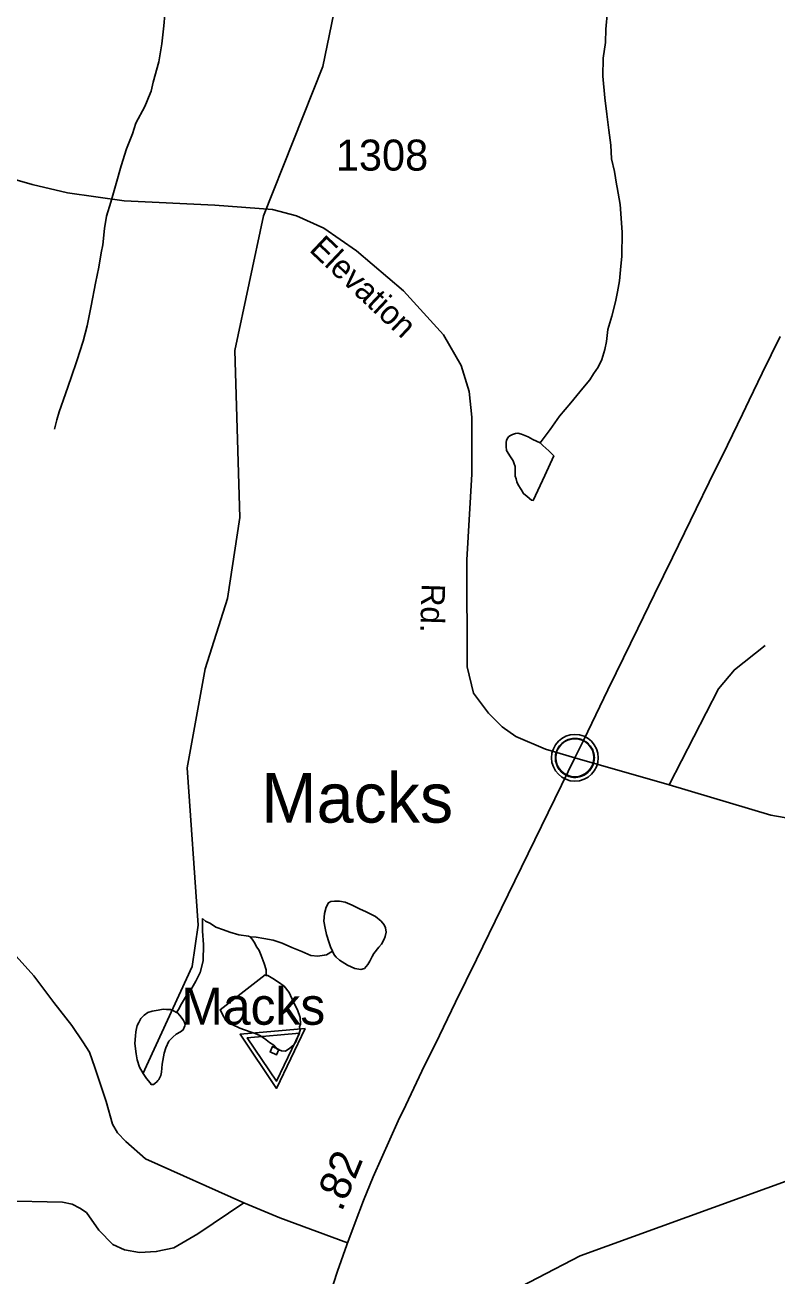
# Model space of a CAD drawing. Extents: x 2082433 to 2279600, y 546599 to 755198.
# Drawn here: x 2128894 to 2131923, y 616158 to 621201 of the extents above; entities that cross this region are included whole.
import ezdxf

# ---------------------------------------------------------------- set-up
doc = ezdxf.new("R2010")
doc.units = 0
for name, color, linetype in [('Exist Civil Demographics Community CELL', 7, 'Continuous'), ('Exist Civil Demographics Community Label', 7, 'Continuous'), ('Exist Hydrographic Creek Single Shore', 7, 'Continuous'), ('Exist Hydrographic Misc Water Feature', 7, 'Continuous'), ('Exist Road Non-System Type 51', 7, 'Continuous'), ('Exist Road Primary NC Attributed', 7, 'Continuous'), ('Exist Road Primary NC Service Mileage Hundredths English Label', 7, 'Continuous'), ('Exist Road Secondary Type 51 Attributed', 7, 'Continuous'), ('Exist Road Secondary Type 51 Label', 7, 'Continuous'), ('Exist Road Secondary Type 51 Number Label', 7, 'Continuous'), ('Exist Survey Geodetic Marker CELL', 7, 'Continuous'), ('Exist Survey Geodetic Marker Label', 7, 'Continuous')]:
    doc.layers.add(name, color=color, linetype=linetype)

msp = doc.modelspace()

# ---------------------------------------------------------------- linework, layer by layer
at = {"layer": 'Exist Civil Demographics Community CELL'}
msp.add_lwpolyline([(2131031.5, 618259.6), (2131032.5, 618265.2), (2131034.3, 618271.8), (2131037.2, 618279), (2131040.1, 618284.7), (2131043.4, 618290.5), (2131047.2, 618295.6), (2131051.2, 618300), (2131055.8, 618304.6), (2131061.3, 618309.2), (2131066.7, 618312.8), (2131071.6, 618315.7), (2131076.7, 618318.1), (2131082.1, 618320.4), (2131087.7, 618322.3), (2131092.1, 618323.4), (2131096.9, 618324.1), (2131101, 618324.9), (2131107.4, 618325.1), (2131111.8, 618325), (2131117.5, 618324.8), (2131122.4, 618324), (2131127.3, 618323), (2131132.3, 618321.6), (2131137.5, 618319.7), (2131144.1, 618316.8), (2131150.4, 618313.3), (2131155.5, 618309.7), (2131160.6, 618305.7), (2131163.9, 618302.6), (2131168.1, 618298.2), (2131171.9, 618293.5), (2131175, 618288.9), (2131178.1, 618283.9), (2131180.6, 618278.7), (2131182.6, 618273.7), (2131184.2, 618268.7), (2131185.5, 618264.1), (2131186.6, 618258.1), (2131187.2, 618253.4), (2131187.5, 618247.4), (2131187.3, 618241.6), (2131186.7, 618235.9), (2131185.8, 618230.4), (2131184.1, 618224.3), (2131182.2, 618218.4), (2131179.9, 618213.4), (2131176.8, 618207.4), (2131173.5, 618202), (2131170.1, 618197.3), (2131165.8, 618192.6), (2131160.5, 618187.6), (2131155.5, 618183.5), (2131150.5, 618180.1), (2131146.2, 618177.6), (2131139.4, 618174.3), (2131132.2, 618171.6), (2131126.3, 618170.2), (2131119.7, 618168.9), (2131115.2, 618168.4), (2131110.8, 618168.1), (2131105.2, 618168.1), (2131100.9, 618168.5), (2131095.3, 618169.3), (2131089.3, 618170.6), (2131084.7, 618171.9), (2131079.6, 618173.8), (2131075, 618175.7), (2131071.1, 618178), (2131064.3, 618182.1), (2131058.7, 618186.3), (2131053.8, 618190.8), (2131049.3, 618195.7), (2131046.1, 618199.6), (2131043.2, 618203.8), (2131039.1, 618210.9), (2131037.3, 618214.5), (2131035.6, 618218.5), (2131033, 618226.7), (2131031.5, 618233.7), (2131030.8, 618238.9), (2131030.5, 618245.2), (2131030.4, 618249.9), (2131031, 618256.4)], close=True, dxfattribs=at)
for centre, radius in [((2131109.1, 618247.2), 94.3), ((2131108.8, 618247.5), 76.7)]:
    msp.add_circle(centre, radius, dxfattribs=at)
at = {"layer": 'Exist Hydrographic Creek Single Shore'}
msp.add_lwpolyline([(2130498.7, 615818.9), (2130788.8, 616062.3), (2131129.9, 616239.1), (2132526.9, 616745.5)], dxfattribs=at)
at = {"layer": 'Exist Hydrographic Misc Water Feature'}
for points in [[(2129368.9, 616973.5), (2129566.7, 617405.8), (2129590.7, 617572.6), (2129546.9, 618206.7), (2129619.9, 618605.4), (2129709.9, 618889), (2129758.9, 619216), (2129738.8, 619888.9), (2129853.8, 620431.2), (2130092.9, 621033.2), (2130199, 621549.4), (2130195.9, 622192.5), (2130261.9, 622332.2), (2130370, 622418.6), (2130460.8, 622442.9), (2130660.9, 622452), (2130735.8, 622493.1), (2130760.8, 622545.2), (2130767, 622945.2)], [(2129012.1, 619571.6), (2129021.9, 619609.9), (2129031.6, 619641.7), (2129057.2, 619714), (2129079.2, 619780), (2129102.9, 619847.8), (2129128.2, 619926.3), (2129144.2, 619988), (2129159.5, 620068.4), (2129177.4, 620160.2), (2129191.1, 620224.3), (2129200.8, 620282.4), (2129206.5, 620314.4), (2129214.1, 620380.5), (2129222.1, 620430.4), (2129239.9, 620486.5), (2129261.4, 620562.8), (2129281.3, 620632.8), (2129303.1, 620702.5), (2129326.7, 620762.6), (2129340.6, 620804.7), (2129376.1, 620872.7), (2129398, 620925), (2129401.7, 620934.9), (2129409.9, 620971), (2129433.3, 621053), (2129445.4, 621125.1), (2129452.8, 621197.3), (2129456.5, 621243)], [(2130969.7, 619516.3), (2130993.3, 619548.5), (2131009.3, 619570.4), (2131047.2, 619624.6), (2131092.8, 619678.6), (2131140.3, 619737.1), (2131168.6, 619770.9), (2131184.4, 619795.3), (2131202.5, 619821.4), (2131217.9, 619853.1), (2131229.7, 619893.5), (2131235.9, 619925.4), (2131241.8, 619973.2), (2131257.6, 620027.6), (2131272.8, 620085.3), (2131280.8, 620125.5), (2131288.4, 620169.3), (2131292.9, 620213.7), (2131298.4, 620269.6), (2131299.9, 620365.5), (2131291.5, 620477.5), (2131279.4, 620545.4), (2131277.1, 620559.6), (2131269.1, 620611.1), (2131256.6, 620661.2), (2131254.3, 620717.1), (2131246.1, 620777.2), (2131238.2, 620841.3), (2131229.5, 620907), (2131221.1, 620995.1), (2131223, 621067), (2131232.8, 621130.8), (2131234, 621184.9), (2131239.8, 621257.1)], [(2130969.7, 619516.3), (2130939.8, 619530.2), (2130921.3, 619540.3), (2130907.4, 619546), (2130893.7, 619551.8), (2130879.3, 619556), (2130869.7, 619553.8), (2130857.6, 619550), (2130849.6, 619545.9), (2130843.4, 619541.9), (2130837.9, 619535.9), (2130833.6, 619525.6), (2130831.7, 619519.8), (2130831.7, 619511.7), (2130831.7, 619501.5), (2130833.8, 619485.8), (2130849.8, 619459.8), (2130859.8, 619443.7), (2130864.1, 619431.7), (2130868, 619421.8), (2130868, 619397.9), (2130868.2, 619382), (2130872.5, 619372.1), (2130874.4, 619360), (2130880.5, 619348.1), (2130892.8, 619328), (2130902.5, 619312), (2130916.6, 619300.1), (2130934.7, 619286), (2130940.8, 619284.3), (2130988.2, 619384.6), (2131024.1, 619464.7), (2131004, 619484.4), (2130979.6, 619506.3), (2130969.7, 619516.3)], [(2130132.7, 617467.2), (2130138.9, 617453.2), (2130146.9, 617443.1), (2130161, 617431.3), (2130193, 617411.4), (2130222.9, 617397.5), (2130247.1, 617393.9), (2130260.9, 617397.9), (2130275, 617414), (2130283, 617427.8), (2130292.7, 617445.8), (2130299, 617457.8), (2130318.7, 617484.1), (2130330.4, 617496), (2130340.6, 617516), (2130344.3, 617526.4), (2130348.2, 617544), (2130346.6, 617562.1), (2130340, 617574.1), (2130328.3, 617588), (2130306.2, 617608), (2130284, 617617.8), (2130267.8, 617625.9), (2130241.8, 617637.6), (2130212.1, 617653.5), (2130184, 617665.4), (2130160, 617669.5), (2130139.9, 617669.3), (2130125.5, 617667.4), (2130115.9, 617663.1), (2130106.3, 617645.2), (2130100.1, 617618.9), (2130098.1, 617589.2), (2130102.4, 617560.9), (2130108.7, 617535.3), (2130118.8, 617501.3), (2130124.7, 617485.4), (2130132.7, 617467.2)], [(2129504, 617220.4), (2129514.1, 617236.7), (2129519.8, 617248.8), (2129544, 617288.6), (2129565.5, 617318.9), (2129581.7, 617346.9), (2129599.4, 617381.2), (2129611.1, 617428.9), (2129612.7, 617495.1), (2129608.6, 617548.9), (2129608.4, 617598.8)], [(2129800.7, 617525.9), (2129794.6, 617527.6), (2129754.8, 617533.7), (2129718.5, 617543.6), (2129692.7, 617553.2), (2129662.7, 617565), (2129640.8, 617578.9), (2129620.3, 617588.9), (2129608.4, 617598.8)], [(2130132.7, 617467.2), (2130108.7, 617453.3), (2130098.9, 617451.2), (2130072.8, 617447), (2130045, 617450.8), (2130008.9, 617466.8), (2129969.1, 617482.6), (2129929.1, 617500.4), (2129892.8, 617512.4), (2129856.3, 617518.3), (2129824.5, 617523.9), (2129800.7, 617525.9)], [(2129865.3, 617370.1), (2129865.5, 617392), (2129857.1, 617418), (2129845, 617449.9), (2129836.8, 617470.2), (2129824.5, 617487.8), (2129819, 617500), (2129808.7, 617515.8), (2129800.7, 617525.9)], [(2129865.3, 617370.1), (2129861.2, 617371.9), (2129679.8, 617231.5), (2129694.3, 617203.4), (2129702.3, 617187.5), (2129728.4, 617171.5), (2129758.5, 617157.6), (2129800.5, 617141.9), (2129820.2, 617136), (2129840.3, 617128.1), (2129858.2, 617116.1), (2129878.5, 617100), (2129896.5, 617088.4), (2129908.6, 617074.4), (2129926.4, 617066.5), (2129942.6, 617064.4), (2129960.5, 617076.7), (2129976.3, 617090.5), (2129984.3, 617102.7), (2129998, 617136.7), (2130002.1, 617148.7), (2129999.8, 617162.8), (2130004.1, 617172.7), (2130001.9, 617200.6), (2129991.6, 617231), (2129975.6, 617262.6), (2129957.8, 617300.6), (2129937.5, 617326.4), (2129915.4, 617342.3), (2129891.4, 617358.1), (2129871.3, 617370), (2129865.3, 617370.1)], [(2129504, 617220.4), (2129508.1, 617218.6), (2129517.8, 617208.6), (2129526.2, 617196.8), (2129532.3, 617188.5), (2129536.2, 617180.6), (2129538.3, 617172.6), (2129538.1, 617166.6), (2129530.3, 617150.7), (2129520, 617142.5), (2129502.6, 617132.6), (2129488.6, 617120.5), (2129472.4, 617104.3), (2129461, 617078.5), (2129454.6, 617056.3), (2129449.3, 617026.3), (2129446.8, 617012.5), (2129443.3, 616980.5), (2129441.3, 616966.2), (2129437.4, 616958.4), (2129433.1, 616950.5), (2129429.4, 616946.1), (2129425.5, 616942.3), (2129417.3, 616934.2), (2129411.5, 616930.2), (2129405.2, 616930.4), (2129401.3, 616930.2), (2129397.2, 616936.4), (2129383.2, 616954.4), (2129369.1, 616973.9), (2129355.2, 617000), (2129345.3, 617029.9), (2129340.8, 617054.1), (2129336.7, 617096), (2129338.8, 617125.8), (2129340.6, 617142.1), (2129342.4, 617156), (2129346.1, 617168), (2129352.5, 617180.1), (2129356.4, 617188), (2129360.1, 617195.9), (2129374, 617210.1), (2129388, 617220.1), (2129406, 617226.3), (2129430, 617230.4), (2129450.3, 617234.2), (2129464, 617232.5), (2129480.2, 617232.5), (2129494, 617226.4), (2129504, 617220.4)]]:
    msp.add_lwpolyline(points, dxfattribs=at)
at = {"layer": 'Exist Road Non-System Type 51'}
for points in [[(2131489, 618137.9), (2131687.4, 618524.5), (2131751.8, 618601.8), (2131875.5, 618699.7)], [(2129774.8, 616452.7), (2129379.5, 616630.7), (2129299.4, 616700.1), (2129265.6, 616735.7), (2129246, 616769.6), (2129221.1, 616862.1), (2129174.8, 616999.2), (2129153.4, 617060.7), (2129126.7, 617101.6), (2129082.2, 617167.5), (2129009.2, 617260.1), (2128929.1, 617368.7), (2128845.4, 617460.3)], [(2129774.8, 616452.7), (2129589.6, 616328), (2129493.5, 616271.1), (2129422.3, 616256.8), (2129354.6, 616253.3), (2129294.1, 616263.9), (2129247.8, 616285.3), (2129190.8, 616342.3), (2129141, 616413.5), (2129114.3, 616432.2), (2129084, 616448.2), (2129044.8, 616455.3), (2128799.2, 616460.7), (2128382.6, 616476.7), (2128208.1, 616484.7)], [(2130193, 616291.3), (2129920.8, 616392.1), (2129774.8, 616452.7)]]:
    msp.add_lwpolyline(points, dxfattribs=at)
at = {"layer": 'Exist Road Primary NC Attributed'}
for points in [[(2131109.1, 618247.2), (2131144.4, 618319.8), (2131241.3, 618521.4), (2131275.1, 618590), (2131362.5, 618768.3), (2131429.1, 618906.1), (2131501.9, 619054.9), (2131574.4, 619203.5), (2131597.9, 619250.4), (2131650.4, 619358.6), (2131723.3, 619507.6), (2131784.4, 619632.9), (2131811.1, 619688.3), (2131864.1, 619797.8), (2131936.2, 619945.5)], [(2130104.8, 616028.8), (2130152.3, 616177.3), (2130190.2, 616283.9), (2130223.7, 616374.4), (2130257.2, 616463.2), (2130296.1, 616558.1), (2130397.5, 616783.2), (2130427.4, 616846.9), (2130493, 616984.1), (2130563.2, 617128), (2130628.4, 617261.5), (2130713, 617434.4), (2130813.3, 617641), (2131109.1, 618247.2)]]:
    msp.add_lwpolyline(points, dxfattribs=at)
at = {"layer": 'Exist Road Secondary Type 51 Attributed'}
for points in [[(2128583.7, 620655.2), (2128922.9, 620558.5), (2129065.1, 620524.3), (2129292.6, 620492.4), (2129658.9, 620474.8), (2129891.3, 620457), (2129987.3, 620432.2), (2130097.3, 620381.8), (2130229, 620290.4), (2130418.1, 620130.1), (2130579.2, 619952.7), (2130650.5, 619828.7), (2130683, 619724.1), (2130693.8, 619620.3), (2130693.8, 619390.2), (2130673.7, 619045.5), (2130675.3, 618613.2), (2130700, 618507.9), (2130760.5, 618427.3), (2130816.2, 618371.5), (2130870.5, 618332.8), (2130989.9, 618281.9), (2131109.1, 618247.2)], [(2131109.1, 618247.2), (2131489, 618137.9), (2131898.4, 618015.5), (2132650.1, 617883.9)]]:
    msp.add_lwpolyline(points, dxfattribs=at)
at = {"layer": 'Exist Survey Geodetic Marker CELL'}
for points in [[(2130022.1, 617155.6), (2129760.4, 617132.4), (2129906.7, 616914.4)], [(2130000, 617137.5), (2129907, 616943.1), (2129789.1, 617118.7)], [(2129916.7, 617071.3), (2129891.2, 617083.5), (2129880.7, 617061.6), (2129906.2, 617049.4)]]:
    msp.add_lwpolyline(points, close=True, dxfattribs=at)

# ---------------------------------------------------------------- texts
at = {"layer": 'Exist Civil Demographics Community Label'}
msp.add_text('Macks', height=200, dxfattribs=at).set_placement((2129845.6, 617985.8))
at = {"layer": 'Exist Road Primary NC Service Mileage Hundredths English Label'}
msp.add_text('.82', height=125, rotation=67.7085, dxfattribs=at).set_placement((2130169.3, 616413.6))
at = {"layer": 'Exist Road Secondary Type 51 Label'}
for s, rotation, p in [('Elevation', 316.6273, (2130034.5, 620291.8)), ('Rd.', 268.2479, (2130491.8, 618950.3))]:
    msp.add_text(s, height=95, rotation=rotation, dxfattribs=at).set_placement(p)
at = {"layer": 'Exist Road Secondary Type 51 Number Label'}
msp.add_text('1308', height=125, dxfattribs=at).set_placement((2130146, 620614.1))
at = {"layer": 'Exist Survey Geodetic Marker Label'}
msp.add_text('Macks', height=150, dxfattribs=at).set_placement((2129523.7, 617171))

doc.saveas('drawing.dxf')
